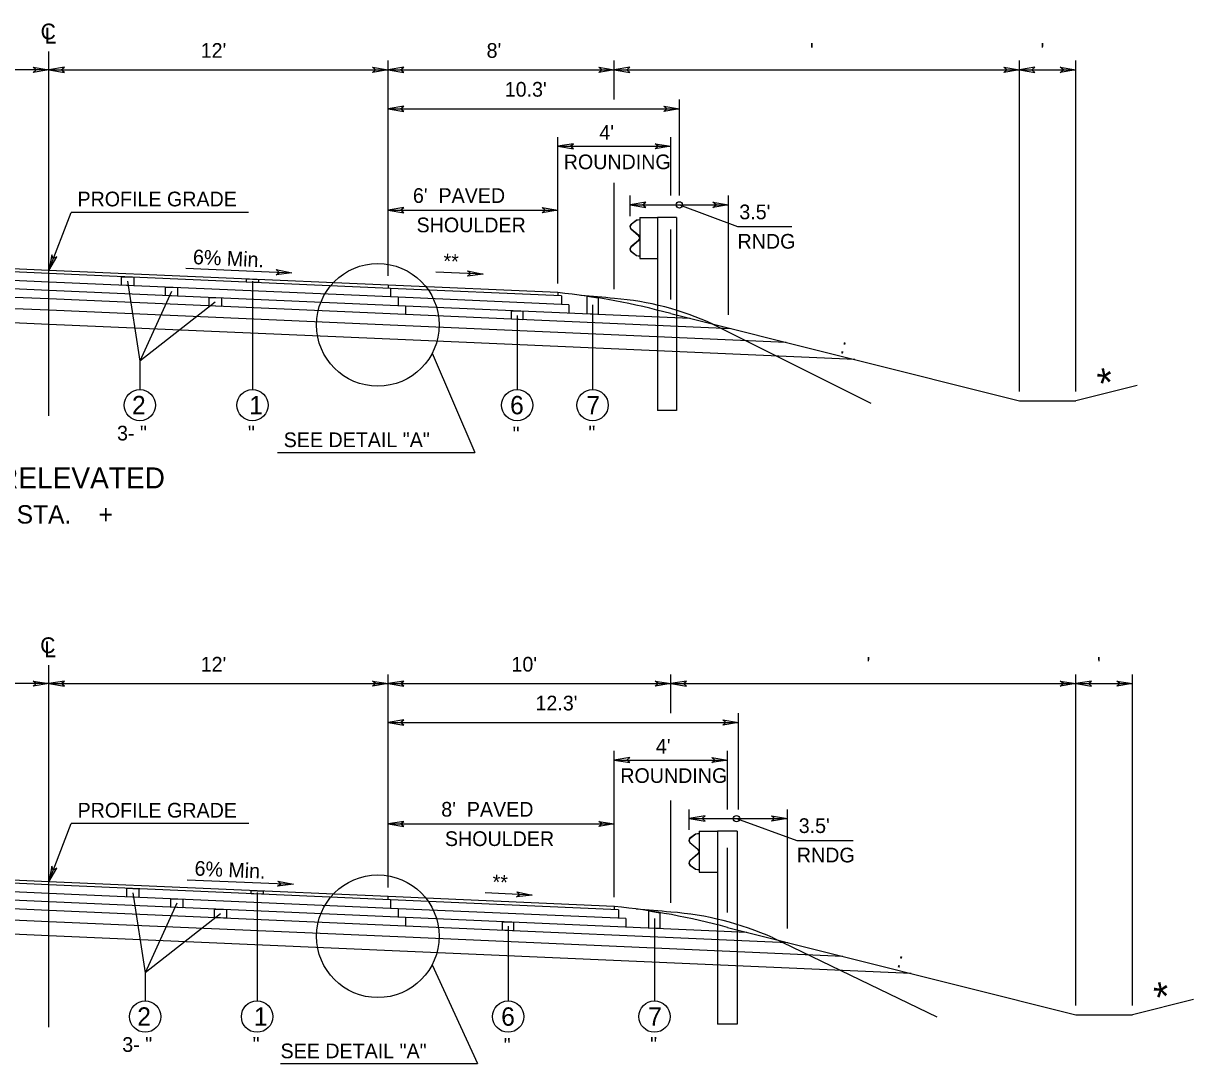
# Model space of a CAD drawing. Extents: x -592 to 1199, y -590 to 416.
# Drawn here: x 1087.7 to 1199.2, y -324.4 to -225.3 of the extents above; entities that cross this region are included whole.
import ezdxf

# ---------------------------------------------------------------- set-up
doc = ezdxf.new("R2010")
doc.units = 0
doc.layers.add('1', color=7, linetype='Continuous')
doc.layers.add('Des_ Drain_ Ftrs', color=7, linetype='Continuous')

msp = doc.modelspace()

# ---------------------------------------------------------------- linework, layer by layer
at = {"layer": '1'}
for p, q in [((1090.11, -262.69), (1090.11, -227.98)), ((1122.44, -249.37), (1122.44, -228.86)), ((1143.99, -232.57), (1143.99, -228.86)), ((1182.58, -260.38), (1182.58, -228.86)), ((1187.97, -260.38), (1187.97, -228.86)), ((1090.11, -229.74), (1057.78, -229.74)), ((1090.11, -229.74), (1122.44, -229.74)), ((1122.44, -229.74), (1143.99, -229.74)), ((1143.99, -229.74), (1182.58, -229.74)), ((1182.58, -229.74), (1187.97, -229.74)), ((1150.19, -241.72), (1150.19, -232.57)), ((1122.44, -233.45), (1150.19, -233.45)), ((1138.6, -250.08), (1138.6, -236.14)), ((1149.38, -241.72), (1149.38, -236.14)), ((1138.6, -237.02), (1149.38, -237.02)), ((1143.99, -250.63), (1143.99, -240.51)), ((1145.5, -243.67), (1145.5, -241.72)), ((1154.88, -253.09), (1154.88, -241.72)), ((1145.5, -242.6), (1154.88, -242.6)), ((1150.19, -242.6), (1155.74, -244.67)), ((1090.11, -248.84), (1092.23, -243.33)), ((1109.15, -243.33), (1092.23, -243.33)), ((1122.44, -243.11), (1138.6, -243.11)), ((1146.09, -244.07), (1145.58, -244.46)), ((1146.11, -244.1), (1145.59, -244.48)), ((1146.41, -244.01), (1146.09, -244.07)), ((1146.41, -244.04), (1146.11, -244.1)), ((1146.41, -243.79), (1146.41, -247.72)), ((1146.41, -243.79), (1148.09, -243.79)), ((1148.09, -243.79), (1148.09, -262.18)), ((1149.92, -243.79), (1148.09, -243.79)), ((1149.92, -243.79), (1149.92, -262.18)), ((1145.56, -244.89), (1146.29, -245.53)), ((1145.58, -244.87), (1146.31, -245.5)), ((1149.38, -251.6), (1149.38, -244.95)), ((1155.74, -244.67), (1160.9, -244.67)), ((1146.29, -245.98), (1145.56, -246.61)), ((1146.31, -246), (1145.58, -246.63)), ((1146.38, -245.71), (1146.38, -245.79)), ((1146.41, -245.71), (1146.41, -245.79)), ((1090.11, -248.84), (1057.77, -247.42)), ((1145.58, -247.04), (1146.09, -247.43)), ((1145.59, -247.02), (1146.11, -247.41)), ((1146.09, -247.43), (1146.41, -247.49)), ((1146.11, -247.41), (1146.41, -247.46)), ((1090.11, -249.95), (1056.51, -248.48)), ((1090.11, -249.14), (1057.43, -247.71)), ((1146.41, -247.72), (1148.09, -247.72)), ((1090.11, -250.75), (1055.59, -249.25)), ((1122.44, -250.25), (1090.11, -248.84)), ((1122.68, -250.56), (1090.11, -249.14)), ((1103.15, -248.64), (1113.26, -249.08)), ((1131.48, -249.2), (1126.99, -249.01)), ((1090.11, -251.56), (1055.59, -250.06)), ((1123.38, -251.4), (1090.11, -249.95)), ((1124.08, -252.24), (1090.11, -250.75)), ((1097.62, -249.87), (1098.79, -257.49)), ((1101.8, -250.85), (1098.79, -257.49)), ((1109.51, -249.86), (1109.51, -260.19)), ((1138.6, -250.96), (1122.44, -250.25)), ((1122.44, -250.25), (1122.44, -250.55)), ((1138.96, -251.27), (1122.68, -250.56)), ((1122.68, -250.56), (1122.68, -251.37)), ((1090.11, -253.99), (1022.94, -251.06)), ((1090.11, -252.64), (1055.59, -251.14)), ((1124.08, -253.05), (1090.11, -251.56)), ((1105.97, -251.87), (1098.79, -257.49)), ((1139.66, -252.11), (1123.38, -251.4)), ((1123.38, -251.4), (1123.38, -252.21)), ((1138.6, -250.96), (1138.6, -251.26)), ((1138.96, -251.27), (1138.96, -252.08)), ((1145.5, -251.73), (1145.5, -251.73)), ((1124.08, -254.13), (1090.11, -252.64)), ((1124.08, -252.24), (1124.08, -253.05)), ((1151.21, -253.42), (1124.08, -252.24)), ((1155.13, -254.4), (1124.08, -253.05)), ((1139.66, -252.11), (1139.66, -252.92)), ((1141.92, -252.11), (1141.92, -260.19)), ((1149.38, -252.96), (1182.58, -261.26)), ((1124.08, -255.47), (1090.11, -253.99)), ((1160.36, -255.71), (1124.08, -254.13)), ((1134.73, -253.15), (1134.73, -260.19)), ((1153.38, -253.97), (1168.43, -261.49)), ((1166.9, -257.34), (1124.08, -255.47)), ((1098.79, -257.49), (1098.79, -260.19)), ((1126.64, -256.72), (1130.69, -266.19)), ((1193.79, -259.81), (1187.97, -261.26)), ((1182.58, -261.26), (1187.97, -261.26)), ((1149.92, -262.18), (1148.09, -262.18)), ((1111.91, -266.19), (1130.69, -266.19)), ((1090.11, -320.94), (1090.11, -286.45)), ((1122.44, -307.62), (1122.44, -287.33)), ((1149.38, -291.03), (1149.38, -287.33)), ((1187.96, -318.87), (1187.96, -287.33)), ((1193.35, -318.87), (1193.35, -287.33)), ((1090.11, -288.21), (1057.78, -288.21)), ((1090.11, -288.21), (1122.44, -288.21)), ((1122.44, -288.21), (1149.38, -288.21)), ((1149.38, -288.21), (1187.96, -288.21)), ((1187.96, -288.21), (1193.35, -288.21)), ((1122.44, -291.91), (1155.81, -291.91)), ((1155.81, -300.19), (1155.81, -291.03)), ((1143.99, -308.56), (1143.99, -294.61)), ((1154.77, -300.19), (1154.77, -294.61)), ((1143.99, -295.49), (1154.77, -295.49)), ((1149.38, -309.1), (1149.38, -299.35)), ((1151.11, -302.14), (1151.11, -300.19)), ((1160.5, -311.55), (1160.5, -300.19)), ((1090.11, -307.08), (1092.24, -301.55)), ((1109.16, -301.55), (1092.24, -301.55)), ((1122.44, -301.58), (1143.99, -301.58)), ((1151.11, -301.07), (1160.5, -301.07)), ((1155.63, -301.07), (1161.39, -303.14)), ((1151.73, -302.54), (1151.2, -302.93)), ((1151.75, -302.56), (1151.22, -302.95)), ((1152.06, -302.48), (1151.73, -302.54)), ((1152.06, -302.51), (1151.75, -302.56)), ((1152.06, -302.25), (1152.06, -306.18)), ((1152.06, -302.25), (1153.81, -302.25)), ((1153.81, -302.25), (1153.81, -320.65)), ((1155.7, -302.25), (1153.81, -302.25)), ((1155.7, -302.25), (1155.7, -320.65)), ((1161.39, -303.14), (1166.74, -303.14)), ((1151.18, -303.36), (1151.94, -303.99)), ((1151.2, -303.34), (1151.96, -303.97)), ((1152.03, -304.18), (1152.03, -304.26)), ((1152.06, -304.18), (1152.06, -304.26)), ((1154.77, -310.01), (1154.77, -303.86)), ((1151.94, -304.44), (1151.18, -305.08)), ((1151.96, -304.47), (1151.2, -305.1)), ((1090.11, -307.38), (1057.43, -305.96)), ((1090.11, -307.08), (1057.77, -305.67)), ((1151.2, -305.51), (1151.73, -305.9)), ((1151.22, -305.49), (1151.75, -305.87)), ((1151.73, -305.9), (1152.06, -305.96)), ((1151.75, -305.87), (1152.06, -305.93)), ((1152.06, -306.18), (1153.81, -306.18)), ((1090.11, -309), (1055.59, -307.5)), ((1090.11, -308.19), (1056.51, -306.73)), ((1122.44, -308.5), (1090.11, -307.08)), ((1122.68, -308.81), (1090.11, -307.38)), ((1103.3, -306.89), (1113.41, -307.33)), ((1090.11, -309.81), (1055.59, -308.3)), ((1123.38, -309.65), (1090.11, -308.19)), ((1098.13, -308.13), (1099.29, -315.76)), ((1109.95, -308.11), (1109.95, -318.44)), ((1143.99, -309.44), (1122.44, -308.5)), ((1122.44, -308.8), (1122.44, -308.5)), ((1144.39, -309.76), (1122.68, -308.81)), ((1122.68, -308.81), (1122.68, -309.62)), ((1136.17, -308.35), (1131.67, -308.15)), ((1090.11, -312.24), (1017.95, -309.09)), ((1090.11, -310.89), (1055.59, -309.38)), ((1124.08, -310.49), (1090.11, -309)), ((1124.08, -311.3), (1090.11, -309.81)), ((1102.3, -309.11), (1099.29, -315.76)), ((1145.08, -310.59), (1123.38, -309.65)), ((1123.38, -309.65), (1123.38, -310.46)), ((1143.99, -309.44), (1143.99, -309.74)), ((1144.39, -309.76), (1144.39, -310.56)), ((1124.08, -312.37), (1090.11, -310.89)), ((1106.48, -310.13), (1099.29, -315.76)), ((1124.08, -310.49), (1124.08, -311.3)), ((1156.6, -311.91), (1124.08, -310.49)), ((1145.08, -310.59), (1145.08, -311.4)), ((1147.81, -310.6), (1147.81, -318.44)), ((1151.11, -310.2), (1151.11, -310.2)), ((1160.52, -312.89), (1124.08, -311.3)), ((1133.87, -311.32), (1133.87, -318.44)), ((1154.77, -311.45), (1187.96, -319.75)), ((1172.28, -315.83), (1090.11, -312.24)), ((1165.75, -314.19), (1124.08, -312.37)), ((1159.12, -312.43), (1174.73, -319.96)), ((1126.62, -315.01), (1130.97, -324.41)), ((1099.29, -315.76), (1099.29, -318.44)), ((1199.18, -318.29), (1193.35, -319.75)), ((1187.96, -319.75), (1193.35, -319.75)), ((1155.7, -320.65), (1153.81, -320.65)), ((1112.18, -324.41), (1130.97, -324.41))]:
    msp.add_line(p, q, dxfattribs=at)
for points in [[(1097.05, -249.44), (1098.2, -249.49), (1098.2, -250.3), (1097.05, -250.25)], [(1108.93, -249.66), (1110.08, -249.71), (1110.08, -250.01), (1108.93, -249.96)], [(1101.22, -250.43), (1102.37, -250.48), (1102.37, -251.29), (1101.22, -251.24)], [(1105.4, -251.42), (1106.55, -251.47), (1106.55, -252.28), (1105.4, -252.23)], [(1141.39, -251.3), (1142.46, -251.47), (1142.46, -253.04), (1141.39, -252.99)], [(1134.19, -252.68), (1135.26, -252.73), (1135.26, -253.54), (1134.19, -253.49)], [(1097.56, -307.71), (1098.7, -307.76), (1098.7, -308.57), (1097.56, -308.52)], [(1101.73, -308.7), (1102.88, -308.75), (1102.88, -309.56), (1101.73, -309.51)], [(1109.38, -307.93), (1110.53, -307.98), (1110.53, -308.28), (1109.38, -308.23)], [(1105.91, -309.69), (1107.05, -309.74), (1107.05, -310.55), (1105.91, -310.5)], [(1147.28, -309.86), (1148.34, -310.03), (1148.34, -311.55), (1147.28, -311.5)], [(1133.34, -310.89), (1134.4, -310.94), (1134.4, -311.75), (1133.34, -311.7)]]:
    msp.add_lwpolyline(points, close=True, dxfattribs=at)
for centre, radius in [((1150.19, -242.6), 0.3), ((1121.46, -254.03), 5.84), ((1098.79, -261.68), 1.49), ((1109.51, -261.68), 1.49), ((1134.73, -261.68), 1.49), ((1141.92, -261.68), 1.49), ((1121.46, -312.28), 5.84), ((1099.29, -319.93), 1.49), ((1109.95, -319.93), 1.49), ((1133.87, -319.93), 1.49), ((1147.81, -319.93), 1.49)]:
    msp.add_circle(centre, radius, dxfattribs=at)
for centre, radius, start, end in [((1145.74, -244.68), 0.278, 126.9799, 229.021), ((1145.74, -244.68), 0.249, 126.9799, 229.021), ((1146.13, -245.71), 0.249, 0, 49.0365), ((1146.13, -245.79), 0.249, 310.9635, 0), ((1146.13, -245.71), 0.278, 0, 49.0365), ((1146.13, -245.79), 0.278, 310.9635, 0), ((1145.74, -246.82), 0.278, 130.979, 233.0201), ((1145.74, -246.82), 0.249, 130.979, 233.0201), ((1131.72, -317.79), 67.19, 74.7602, 84.1188), ((1133.17, -352.18), 101.24, 83.8633, 85.6775), ((1141.87, -278.8), 27.37, 65.1374, 85.5513), ((1137.11, -376.27), 67.19, 74.7602, 84.1188)]:
    msp.add_arc(centre, radius, start, end, dxfattribs=at)
msp.add_ellipse((1155.63, -301.07), major_axis=(-0.311, 0), ratio=0.964041, dxfattribs=at)
for centre, major_axis, start_param, end_param in [((1151.37, -303.15), (-0.288, 0), 5.35781, 7.138763), ((1151.37, -303.15), (-0.258, 0), 5.35781, 7.138763), ((1151.77, -304.18), (0.258, 0), 0, 0.855848), ((1151.77, -304.26), (0.258, 0), 5.427337, 6.283185), ((1151.77, -304.18), (0.288, 0), 0, 0.855848), ((1151.77, -304.26), (0.288, 0), 5.427337, 6.283185), ((1151.37, -305.29), (-0.288, 0), 5.427608, 7.208561), ((1151.37, -305.29), (-0.258, 0), 5.427608, 7.208561), ((1138.16, -410.64), (105.02, 0), 1.463691, 1.495354), ((1147.18, -337.26), (28.39, 0), 1.136862, 1.493152)]:
    msp.add_ellipse(centre, major_axis=major_axis, ratio=0.964041, start_param=start_param, end_param=end_param, dxfattribs=at)
at = {"layer": 'Des_ Drain_ Ftrs'}
for points in [[(1090.11, -229.74), (1088.62, -229.99), (1088.91, -229.74), (1088.62, -229.49)], [(1090.11, -229.74), (1091.6, -229.99), (1091.3, -229.74), (1091.6, -229.49)], [(1122.44, -229.74), (1120.95, -229.99), (1121.24, -229.74), (1120.95, -229.49)], [(1122.44, -229.74), (1123.93, -229.99), (1123.63, -229.74), (1123.93, -229.49)], [(1143.99, -229.74), (1142.5, -229.99), (1142.8, -229.74), (1142.5, -229.49)], [(1143.99, -229.74), (1145.48, -229.99), (1145.18, -229.74), (1145.48, -229.49)], [(1182.58, -229.74), (1181.09, -229.99), (1181.38, -229.74), (1181.09, -229.49)], [(1182.58, -229.74), (1184.07, -229.99), (1183.77, -229.74), (1184.07, -229.49)], [(1187.97, -229.74), (1186.48, -229.99), (1186.77, -229.74), (1186.48, -229.49)], [(1122.44, -233.45), (1123.93, -233.69), (1123.63, -233.45), (1123.93, -233.2)], [(1150.19, -233.45), (1148.7, -233.69), (1148.99, -233.45), (1148.7, -233.2)], [(1138.6, -237.02), (1140.09, -237.27), (1139.79, -237.02), (1140.09, -236.77)], [(1149.38, -237.02), (1147.89, -237.27), (1148.18, -237.02), (1147.89, -236.77)], [(1122.44, -243.11), (1123.93, -243.36), (1123.63, -243.11), (1123.93, -242.86)], [(1138.6, -243.11), (1137.11, -243.36), (1137.41, -243.11), (1137.11, -242.86)], [(1145.5, -242.6), (1146.98, -242.85), (1146.69, -242.6), (1146.98, -242.35)], [(1154.88, -242.6), (1153.39, -242.85), (1153.69, -242.6), (1153.39, -242.35)], [(1090.11, -248.84), (1090.87, -247.54), (1090.53, -247.72), (1090.41, -247.36)], [(1113.26, -249.08), (1111.76, -249.26), (1112.07, -249.03), (1111.78, -248.77)], [(1131.48, -249.2), (1129.99, -249.39), (1130.29, -249.15), (1130.01, -248.89)], [(1090.11, -288.21), (1088.62, -288.46), (1088.91, -288.21), (1088.62, -287.96)], [(1090.11, -288.21), (1091.6, -288.46), (1091.3, -288.21), (1091.6, -287.96)], [(1122.44, -288.21), (1120.95, -288.46), (1121.24, -288.21), (1120.95, -287.96)], [(1122.44, -288.21), (1123.93, -288.46), (1123.63, -288.21), (1123.93, -287.96)], [(1149.38, -288.21), (1147.89, -288.46), (1148.18, -288.21), (1147.89, -287.96)], [(1149.38, -288.21), (1150.87, -288.46), (1150.57, -288.21), (1150.87, -287.96)], [(1187.96, -288.21), (1186.48, -288.46), (1186.77, -288.21), (1186.48, -287.96)], [(1187.96, -288.21), (1189.45, -288.46), (1189.16, -288.21), (1189.45, -287.96)], [(1193.35, -288.21), (1191.86, -288.46), (1192.16, -288.21), (1191.86, -287.96)], [(1122.44, -291.91), (1123.93, -292.16), (1123.63, -291.91), (1123.93, -291.66)], [(1155.81, -291.91), (1154.32, -292.16), (1154.61, -291.91), (1154.32, -291.66)], [(1143.99, -295.49), (1145.48, -295.73), (1145.18, -295.49), (1145.48, -295.24)], [(1154.77, -295.49), (1153.28, -295.73), (1153.57, -295.49), (1153.28, -295.24)], [(1151.11, -301.07), (1152.66, -301.32), (1152.35, -301.07), (1152.66, -300.82)], [(1160.5, -301.07), (1158.95, -301.32), (1159.26, -301.07), (1158.95, -300.82)], [(1122.44, -301.58), (1123.93, -301.83), (1123.63, -301.58), (1123.93, -301.33)], [(1143.99, -301.58), (1142.5, -301.83), (1142.8, -301.58), (1142.5, -301.33)], [(1090.11, -307.08), (1090.87, -305.78), (1090.53, -305.97), (1090.41, -305.61)], [(1113.41, -307.33), (1111.91, -307.52), (1112.22, -307.28), (1111.93, -307.02)], [(1136.17, -308.35), (1134.67, -308.53), (1134.97, -308.3), (1134.69, -308.04)]]:
    msp.add_lwpolyline(points, close=True, dxfattribs=at)

# ---------------------------------------------------------------- texts
at = {"layer": '1'}
for s, height, p in [("12'", 1.4, (1104.58, -228.59)), ("8'", 1.4, (1131.82, -228.59)), ("  '", 1.4, (1161.59, -228.59)), (" '", 1.4, (1184.08, -228.59)), ("10.3'", 1.4, (1133.55, -232.29)), ("4'", 1.4, (1142.56, -236.4)), ('ROUNDING', 1.4, (1139.17, -239.2)), ('PROFILE GRADE', 1.4, (1092.84, -242.74)), ("6'  PAVED", 1.4, (1124.8, -242.41)), ("3.5'", 1.4, (1155.9, -243.97)), ('SHOULDER', 1.4, (1125.15, -245.21)), ('RNDG', 1.4, (1155.73, -246.77)), ('2', 1.75, (1098.04, -262.55)), ('1', 1.75, (1109.21, -262.55)), ('6', 1.75, (1134.06, -262.55)), ('7', 1.75, (1141.33, -262.55)), ('3- "', 1.4, (1096.61, -265.04)), (' "', 1.4, (1108.56, -265.04)), (' "', 1.4, (1133.78, -265.13)), ('  "', 1.4, (1140.48, -265.04)), ('SEE DETAIL "A"', 1.4, (1112.49, -265.68)), ('SUPERELEVATED', 2, (1077.99, -269.61)), ('STA.    +      TO STA.    +     ', 1.75, (1070.08, -272.96)), ("12'", 1.4, (1104.58, -287.06)), ("10'", 1.4, (1134.19, -287.06)), ("  '", 1.4, (1166.98, -287.06)), (" '", 1.4, (1189.46, -287.06)), ("12.3'", 1.4, (1136.48, -290.76)), ("4'", 1.4, (1147.95, -294.87)), ('ROUNDING', 1.4, (1144.56, -297.67)), ('PROFILE GRADE', 1.4, (1092.85, -300.97)), ("8'  PAVED", 1.4, (1127.5, -300.88)), ("3.5'", 1.4, (1161.56, -302.44)), ('SHOULDER', 1.4, (1127.85, -303.68)), ('RNDG', 1.4, (1161.38, -305.24)), ('2', 1.75, (1098.54, -320.8)), ('1', 1.75, (1109.65, -320.8)), ('6', 1.75, (1133.21, -320.8)), ('7', 1.75, (1147.22, -320.8)), ('3- "', 1.4, (1097.11, -323.29)), (' "', 1.4, (1109.01, -323.29)), (' "', 1.4, (1132.93, -323.38)), ('  "', 1.4, (1146.36, -323.29)), ('SEE DETAIL "A"', 1.4, (1112.19, -323.9))]:
    msp.add_text(s, height=height, dxfattribs=at).set_placement(p)
for s, height, rotation, p in [('6% Min.', 1.4, 357.3731, (1103.82, -248.24)), ('**', 1.4, 357.2167, (1127.67, -248.64)), (' : ', 1.4, 345.7718, (1164.93, -256.56)), ('*', 2.8, 12.8479, (1190.43, -261.07)), ('6% Min.', 1.4, 357.3731, (1103.97, -306.49)), ('**', 1.4, 357.2158, (1132.35, -307.79)), (' : ', 1.4, 345.7718, (1170.32, -315.05)), ('*', 2.8, 12.8479, (1195.81, -319.56))]:
    msp.add_text(s, height=height, rotation=rotation, dxfattribs=at).set_placement(p)
at = {"layer": 'Des_ Drain_ Ftrs'}
for s, p in [('C', (1089.33, -226.83)), ('L', (1089.72, -227.23)), ('C', (1089.29, -285.3)), ('L', (1089.69, -285.69))]:
    msp.add_text(s, height=1.5, dxfattribs=at).set_placement(p)

doc.saveas('drawing.dxf')
